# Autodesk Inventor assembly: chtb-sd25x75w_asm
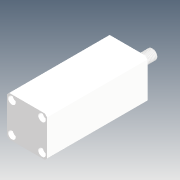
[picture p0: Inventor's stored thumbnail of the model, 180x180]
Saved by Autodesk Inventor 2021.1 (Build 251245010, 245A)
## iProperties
Company: Microsoft
Created: 2018-05
Part Number: chtb-sd25x75w_asm
Description: STEP AP214
Document SubType Name: Assembly
Designer: user
Title: chtb-sd25x75w_asm.STEP
Author: Windows
Revision Number: ÈÎºÎ
Sending System: SolidWorks 2015
Preprocessor: SwSTEP 2.0
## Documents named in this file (4)
- D:\Vault_2016\Projekty\Clamptek\Hydraulic\CHTB\CHTB-25\Inventor\chtb-sd25x75w\chtb-sd25x75w_asm.iam
- D:\Vault_2016\Projekty\Clamptek\Hydraulic\CHTB\CHTB-25\Inventor\chtb-sd25x75w\CHTB-25QG.ipt
- D:\Vault_2016\Projekty\Clamptek\Hydraulic\CHTB\CHTB-25\Inventor\chtb-sd25x75w\CHTB-SD25X75NBT.ipt
- D:\Vault_2016\Projekty\Clamptek\Hydraulic\CHTB\CHTB-25\Inventor\chtb-sd25x75w\CHTB-SD25X75WHSG.ipt
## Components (3 placed, 3 different names)
1. CHTB-25QG_1
2. CHTB-SD25X75NBT_2
3. CHTB-SD25X75WHSG_3
